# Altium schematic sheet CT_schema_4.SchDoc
size 257 x 245 mm
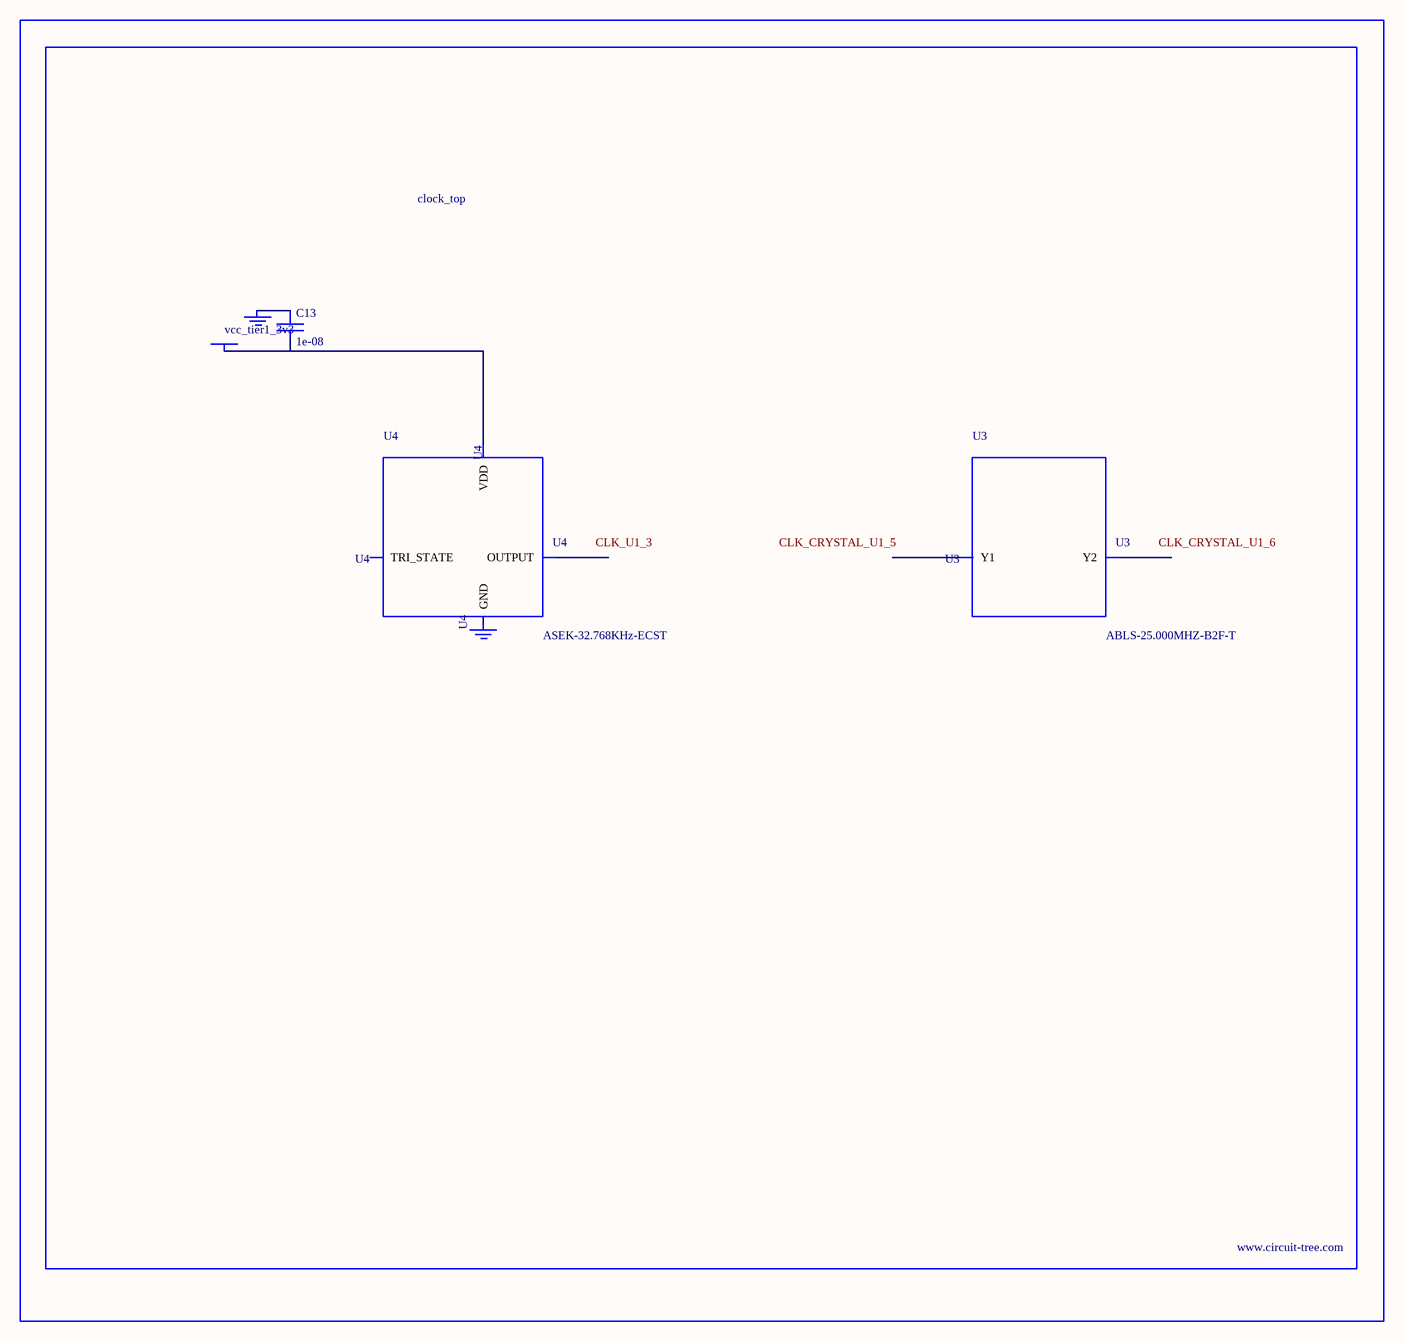
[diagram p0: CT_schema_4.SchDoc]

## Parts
BORDER3  (no value)
C13  1e-08  [C0402]
GND_INSTANCE_3_0  (no value)
GND_INSTANCE_3_1  (no value)
POWER_INSTANCE_3_0  vcc_tier1_3v3
U3  ABLS-25.000MHZ-B2F-T  [ABLS-25.000MHZ-B2F-T]
U4  ASEK-32.768KHz-ECST  [ASEK]

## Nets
NetC13_1: C13.1 GND_INSTANCE_3_0.0(GND)
NetC13_2: C13.2 POWER_INSTANCE_3_0.0(PWR) U4.4(VDD)

Not connected (* = marked no-connect by the designer): GND_INSTANCE_3_1 0(GND); U3 1(Y1) 2(Y2); U4 1(TRI_STATE) 2(GND) 3(OUTPUT)

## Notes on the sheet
- Labels drawn without touching a wire or pin: CLK_CRYSTAL_U1_5, CLK_CRYSTAL_U1_6, CLK_U1_3

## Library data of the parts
BORDER3 = BORDER_PAGE3
C13 = C0402C103K3RAC
GND_INSTANCE_3_0 GND_INSTANCE_3_1 = GND
POWER_INSTANCE_3_0 = PWR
